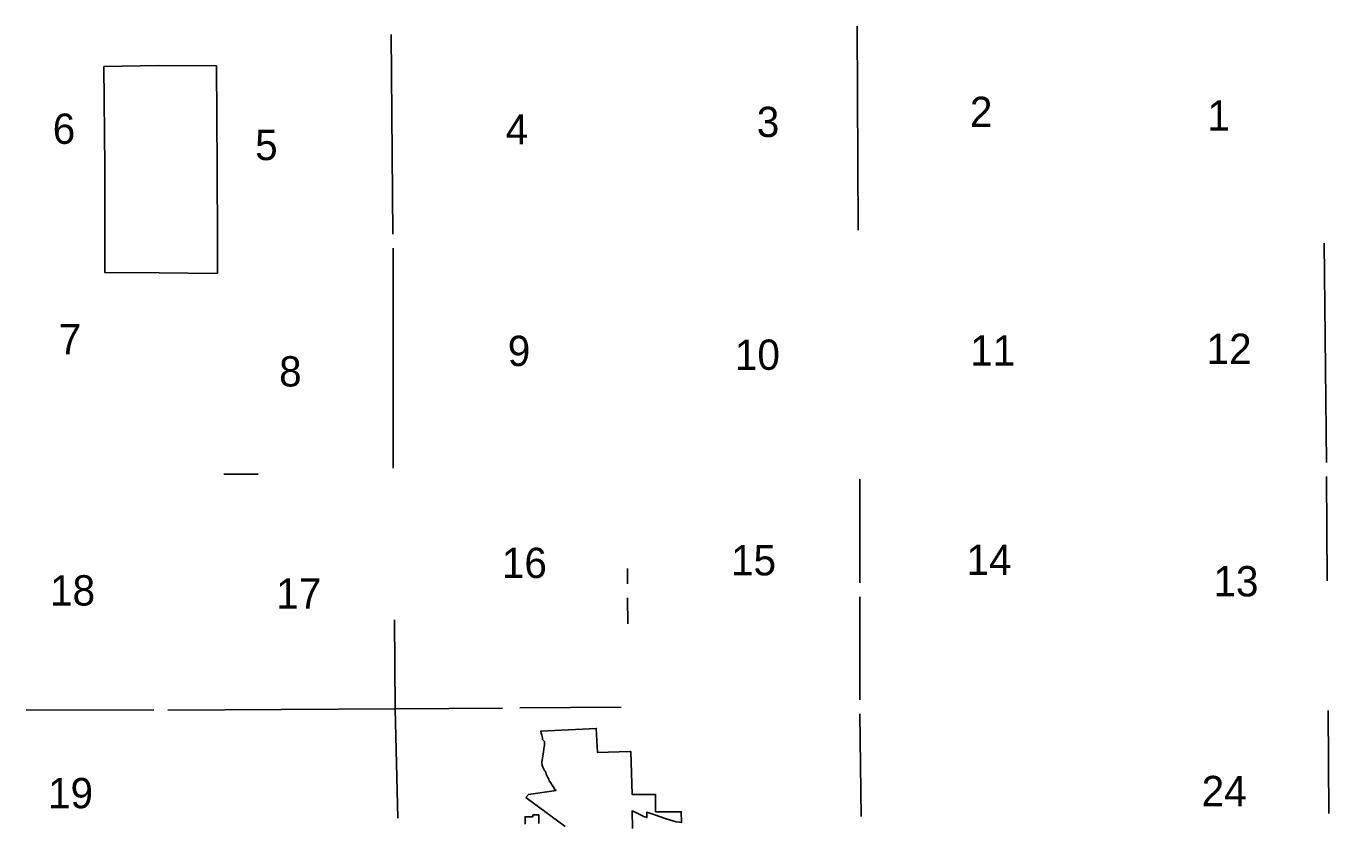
# Model space of a CAD drawing. Extents: x -2251611 to -2054719, y -2227156 to -2099355.
# Drawn here: x -2154325 to -2124807, y -2117859 to -2099809 of the extents above; entities that cross this region are included whole.
import ezdxf

# ---------------------------------------------------------------- set-up
doc = ezdxf.new("R2010")
doc.units = 0
for name, color, linetype in [('tdCoCorpBndry', 7, 'Continuous'), ('tdCoSectLinePart', 7, 'Continuous'), ('tdCoSectNmbr', 7, 'Continuous')]:
    doc.layers.add(name, color=color, linetype=linetype)

msp = doc.modelspace()

# ---------------------------------------------------------------- linework, layer by layer
at = {"layer": 'tdCoCorpBndry'}
msp.add_lwpolyline([(-2152561, -2100727), (-2151325, -2100699), (-2150011, -2100708), (-2149999, -2103020), (-2149991, -2104684), (-2149990, -2105410), (-2151313, -2105402), (-2152537, -2105394), (-2152539, -2104693), (-2152543, -2103030), (-2152543, -2103013), (-2152543, -2103005)], close=True, dxfattribs=at)
for points in [[(-2142110, -2117938), (-2143001, -2117283), (-2142943, -2117214), (-2142366, -2117133), (-2142316, -2117125), (-2142343, -2117102), (-2142375, -2117046), (-2142408, -2117007), (-2142443, -2116946), (-2142470, -2116902), (-2142482, -2116867), (-2142503, -2116829), (-2142524, -2116787), (-2142540, -2116756), (-2142549, -2116724), (-2142551, -2116702), (-2142571, -2116684), (-2142591, -2116641), (-2142618, -2116593), (-2142631, -2116554), (-2142636, -2116516), (-2142640, -2116477), (-2142634, -2116434), (-2142625, -2116398), (-2142616, -2116337), (-2142604, -2116259), (-2142597, -2116175), (-2142589, -2116142), (-2142580, -2116088), (-2142576, -2116043), (-2142580, -2116015), (-2142601, -2115992), (-2142622, -2115973), (-2142628, -2115933), (-2142637, -2115870), (-2142654, -2115826), (-2142666, -2115783), (-2141408, -2115719), (-2141379, -2116263), (-2140644, -2116239), (-2140626, -2116238), (-2140592, -2117218), (-2140067, -2117215), (-2140062, -2117605), (-2139480, -2117607), (-2139478, -2117850), (-2139522, -2117844), (-2139599, -2117832), (-2139724, -2117800), (-2139842, -2117760), (-2140078, -2117678), (-2140259, -2117612), (-2140258, -2117738), (-2140329, -2117710), (-2140373, -2117690), (-2140433, -2117662), (-2140496, -2117632), (-2140593, -2117587), (-2140586, -2117986)], [(-2143019, -2117885), (-2143019, -2117719), (-2142842, -2117718), (-2142842, -2117677), (-2142706, -2117679), (-2142708, -2117873)]]:
    msp.add_lwpolyline(points, dxfattribs=at)
at = {"layer": 'tdCoSectLinePart'}
for points in [[(-2135499, -2099809), (-2135470, -2104432)], [(-2146013, -2104525), (-2146050, -2099999)], [(-2146011, -2104841), (-2146010, -2109821)], [(-2124918, -2104723), (-2124862, -2109696)], [(-2149846, -2109958), (-2149068, -2109962)], [(-2135435, -2112418), (-2135434, -2110075)], [(-2124859, -2110012), (-2124845, -2112377)], [(-2140699, -2112099), (-2140697, -2112443)], [(-2140695, -2112760), (-2140692, -2113352)], [(-2135436, -2115073), (-2135435, -2112734)], [(-2145981, -2113260), (-2145963, -2115275)], [(-2151110, -2115302), (-2145963, -2115275)], [(-2145963, -2115275), (-2143533, -2115257)], [(-2145963, -2115275), (-2145904, -2117755)], [(-2143136, -2115254), (-2140841, -2115238)], [(-2154325, -2115295), (-2151427, -2115303)], [(-2135407, -2117714), (-2135434, -2115390)], [(-2124827, -2115313), (-2124807, -2117646)]]:
    msp.add_lwpolyline(points, dxfattribs=at)

# ---------------------------------------------------------------- texts
at = {"layer": 'tdCoSectNmbr'}
for s, height, rotation, p in [('2', 686, 0.0207, (-2132941, -2102096)), ('3', 686, 0.02, (-2137769, -2102322)), ('1', 686, 0.0214, (-2127561, -2102180)), ('6', 686, 0.0176, (-2153721, -2102477)), ('4', 686, 0.0191, (-2143459, -2102491)), ('5', 686, 0.0183, (-2149135, -2102845)), ('7', 686, 0.0176, (-2153585, -2107242)), ('9', 686, 0.0191, (-2143411, -2107509)), ('10', 686.4, 0.0198, (-2138266, -2107596)), ('11', 686.4, 0.0205, (-2132935, -2107499)), ('12', 686.4, 0.0213, (-2127579, -2107462)), ('8', 686, 0.0183, (-2148592, -2107973)), ('16', 686.4, 0.0189, (-2143546, -2112312)), ('15', 686.4, 0.0197, (-2138354, -2112252)), ('14', 686.4, 0.0205, (-2133019, -2112242)), ('13', 686.4, 0.0213, (-2127424, -2112728)), ('18', 686.4, 0.0174, (-2153782, -2112935)), ('17', 686.4, 0.0182, (-2148657, -2113006)), ('19', 686.4, 0.0173, (-2153828, -2117527)), ('24', 686.4, 0.0211, (-2127691, -2117480))]:
    msp.add_text(s, height=height, rotation=rotation, dxfattribs=at).set_placement(p)

doc.saveas('drawing.dxf')
